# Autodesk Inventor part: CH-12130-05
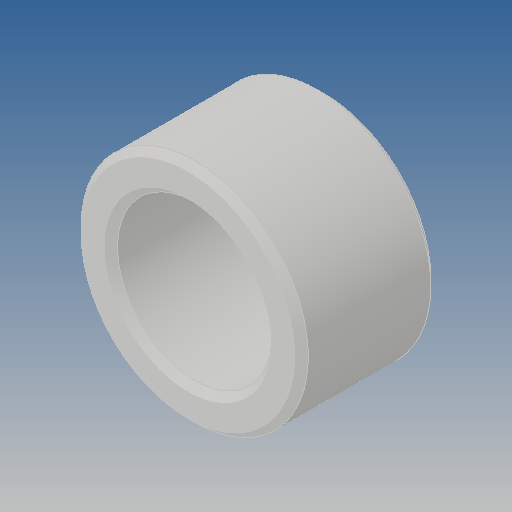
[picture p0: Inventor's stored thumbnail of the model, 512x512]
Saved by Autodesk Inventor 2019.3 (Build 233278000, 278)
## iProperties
Created: 2017-11
Part Number: CH-12130-05
Material: Ogólny
Document SubType Name: Modeling
Designer: Admin
Density: 1 g/cm^3
Appearance: Domyślna
Author: Admin
Revision Number: ÈÎºÎ
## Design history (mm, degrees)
feature "µ¹½Ç1"
node "Bryła1"
